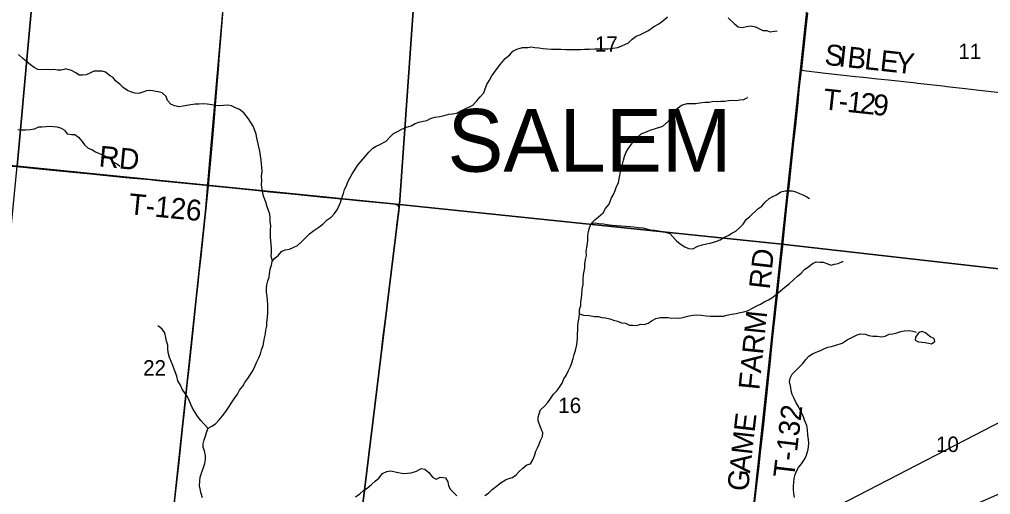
# Model space of a CAD drawing. Extents: x 831 to 1552, y 430 to 870.
# Drawn here: x 993.3 to 1046.1, y 699.2 to 725.1 of the extents above; entities that cross this region are included whole.
import ezdxf

# ---------------------------------------------------------------- set-up
doc = ezdxf.new("R2010")
doc.units = 0
for name, color, linetype in [('GM_X_Corporation', 7, 'Continuous'), ('GM_X_Minor_Lake', 7, 'Continuous'), ('GM_X_Minor_River', 7, 'Continuous'), ('GM_X_Rail_Line', 7, 'Continuous'), ('GM_X_Section_Text', 7, 'Continuous'), ('GM_X_Township_Road', 7, 'Continuous'), ('GM_X_Township_Road_Text', 7, 'Continuous'), ('GM_X_Township_Text', 7, 'Continuous'), ('GM_X_US_Route', 7, 'Continuous'), ('SH_Text', 7, 'Continuous')]:
    doc.layers.add(name, color=color, linetype=linetype)

msp = doc.modelspace()

# ---------------------------------------------------------------- linework, layer by layer
at = {"layer": 'GM_X_Corporation'}
for points in [[(974.695, 738.984), (994.975, 737.085), (993.147, 717.069), (972.322, 718.961)], [(994.975, 737.085), (1015.357, 735.031), (1013.944, 715), (993.147, 717.069)], [(1015.357, 735.031), (1036.878, 732.803), (1034.738, 712.834), (1013.944, 715)], [(1036.878, 732.803), (1052.432, 731.297), (1052.759, 730.026), (1055.607, 718.06), (1054.834, 710.548), (1034.738, 712.834)], [(993.147, 717.069), (1013.944, 715), (1011.587, 695.769), (991.236, 697.554)], [(1034.738, 712.834), (1032.694, 693.772), (1011.587, 695.769), (1013.944, 715)], [(1034.738, 712.834), (1054.834, 710.548), (1052.831, 691.774), (1032.694, 693.772)]]:
    msp.add_lwpolyline(points, close=True, dxfattribs=at)
at = {"layer": 'GM_X_Minor_Lake'}
for points in [[(1042.005, 707.771), (1041.987, 707.62), (1042.176, 707.519), (1042.358, 707.509), (1042.524, 707.492), (1042.714, 707.451), (1042.88, 707.411), (1043.005, 707.511)], [(1043.005, 707.511), (1043.057, 707.552), (1043.021, 707.711), (1042.847, 707.774), (1042.682, 707.898), (1042.555, 708.006), (1042.366, 708.091), (1042.191, 708.041), (1042.005, 707.771)]]:
    msp.add_lwpolyline(points, dxfattribs=at)
at = {"layer": 'GM_X_Minor_River'}
for points in [[(1017.272, 720.076), (1017.517, 720.195), (1017.93, 720.388), (1018.145, 720.636), (1018.33, 720.839), (1018.53, 721.072), (1018.601, 721.283), (1018.702, 721.517), (1018.833, 721.743), (1018.965, 721.991), (1019.119, 722.187), (1019.413, 722.608), (1019.697, 722.924), (1019.943, 723.134), (1020.112, 723.329), (1020.334, 723.433), (1020.632, 723.536), (1020.922, 723.534), (1021.112, 723.562), (1021.302, 723.523), (1021.53, 723.513), (1021.759, 723.473), (1022.215, 723.431), (1022.527, 723.443), (1022.725, 723.434), (1022.984, 723.424), (1023.197, 723.415), (1023.593, 723.418), (1023.791, 723.424), (1024.004, 723.437), (1024.286, 723.442), (1024.56, 723.448), (1024.797, 723.453), (1025.025, 723.458), (1025.276, 723.464), (1025.551, 723.492), (1025.81, 723.527), (1026.032, 723.616), (1026.391, 723.787), (1026.606, 723.982), (1026.821, 724.147), (1027.02, 724.213), (1027.241, 724.325), (1027.479, 724.459), (1027.755, 724.654), (1028.053, 724.81), (1028.245, 724.968), (1028.514, 725.2)], [(1031.825, 725.14), (1032.165, 724.811), (1032.369, 724.65), (1032.574, 724.618), (1032.811, 724.676), (1033.078, 724.712), (1033.298, 724.657), (1033.495, 724.556), (1033.707, 724.448), (1033.897, 724.447), (1034.11, 724.384), (1034.331, 724.412), (1034.484, 724.426)], [(995.774, 722.357), (995.547, 722.3), (995.352, 722.302), (995.155, 722.331), (994.95, 722.322), (994.753, 722.327), (994.532, 722.311), (994.282, 722.326), (994.081, 722.438), (993.872, 722.58), (993.65, 722.776), (993.458, 722.933), (993.229, 723.151)], [(1007.044, 711.927), (1006.971, 712.168), (1006.988, 712.372), (1006.983, 712.615), (1006.969, 712.82), (1006.948, 713.009), (1006.927, 713.214), (1006.929, 713.411), (1006.923, 713.608), (1006.941, 713.835), (1006.92, 714.063), (1006.907, 714.275), (1006.886, 714.472), (1006.819, 714.67), (1006.753, 714.86), (1006.693, 715.057), (1006.627, 715.262), (1006.545, 715.452), (1006.486, 715.71), (1006.436, 716.067), (1006.461, 716.271), (1006.441, 716.536), (1006.481, 716.778), (1006.461, 717.013), (1006.44, 717.202), (1006.419, 717.407), (1006.383, 717.634), (1006.355, 717.9), (1006.304, 718.12), (1006.194, 718.613), (1006.15, 718.817), (1006.084, 719.015), (1005.987, 719.25), (1005.867, 719.448), (1005.732, 719.654), (1005.483, 719.967), (1005.249, 720.15), (1005.022, 720.243), (1004.809, 720.359), (1004.604, 720.391), (1004.375, 720.37), (1004.177, 720.357), (1003.942, 720.382), (1003.736, 720.414), (1003.485, 720.447), (1003.295, 720.464), (1003.059, 720.451), (1002.83, 720.438), (1002.594, 720.402), (1002.38, 720.366), (1002.182, 720.345), (1001.938, 720.31), (1001.725, 720.35), (1001.52, 720.427), (1001.325, 720.641), (1001.258, 720.869), (1001.032, 721.06), (1000.826, 721.115), (1000.606, 721.147), (1000.416, 721.194), (1000.187, 721.174), (999.981, 721.108), (999.767, 721.019), (999.562, 721.036), (999.372, 721.091), (999.16, 721.191), (998.925, 721.36), (998.729, 721.543), (998.502, 721.712), (998.367, 721.902), (998.17, 722.002), (997.958, 722.193), (997.768, 722.241), (997.54, 722.25), (997.319, 722.245), (997.113, 722.141), (996.914, 722.037), (996.723, 722.016), (996.533, 722.025), (996.336, 722.156), (996.116, 722.279), (995.904, 722.334), (995.771, 722.359)], [(1022.182, 704.464), (1022.329, 704.675), (1022.521, 704.878), (1022.645, 705.067), (1022.784, 705.285), (1022.877, 705.512), (1023.009, 705.701), (1023.141, 705.973), (1023.242, 706.192), (1023.312, 706.381), (1023.383, 706.616), (1023.453, 706.835), (1023.524, 707.062), (1023.579, 707.297), (1023.604, 707.494), (1023.629, 707.767), (1023.631, 707.957), (1023.648, 708.161), (1023.65, 708.374), (1023.66, 708.579), (1023.708, 708.844), (1023.74, 709.071), (1023.735, 709.276), (1023.805, 709.503), (1023.799, 709.7), (1023.847, 709.897), (1023.864, 710.094), (1023.874, 710.39), (1023.93, 710.639), (1023.925, 710.897), (1023.943, 711.178), (1023.983, 711.367), (1024.015, 711.556), (1024.032, 711.746), (1024.057, 712.003), (1024.112, 712.222), (1024.092, 712.442), (1024.124, 712.647), (1024.171, 712.851), (1024.181, 713.056), (1024.191, 713.298), (1024.231, 713.518), (1024.286, 713.729), (1024.365, 713.956), (1024.572, 714.151), (1024.772, 714.316), (1025.017, 714.541), (1025.149, 714.782), (1025.342, 715.015), (1025.474, 715.347), (1025.59, 715.536), (1025.676, 715.762), (1025.747, 715.974), (1025.863, 716.177), (1025.887, 716.382), (1025.92, 716.571), (1025.96, 716.783), (1026.015, 716.979), (1026.078, 717.183), (1026.126, 717.41), (1026.188, 717.599), (1026.251, 717.795), (1026.382, 718.014), (1026.506, 718.202), (1026.668, 718.412), (1026.845, 718.615), (1027.083, 718.84), (1027.381, 718.944), (1027.58, 719.04), (1028.26, 719.246), (1028.582, 719.516), (1028.775, 719.779), (1028.86, 719.968), (1029.084, 720.231), (1029.283, 720.396), (1029.596, 720.492), (1029.794, 720.482), (1030.061, 720.48), (1030.259, 720.516), (1030.571, 720.551), (1030.792, 720.564), (1031.029, 720.607), (1031.227, 720.598), (1031.425, 720.619), (1031.63, 720.617), (1031.844, 720.653), (1032.05, 720.673), (1032.248, 720.649), (1032.446, 720.685), (1032.667, 720.706), (1032.866, 720.81), (1032.858, 720.817)], [(1003.399, 701.34), (1003.34, 701.592), (1003.265, 701.783), (1003.275, 701.972), (1003.33, 702.2), (1003.393, 702.405), (1003.456, 702.601), (1003.549, 702.836), (1003.741, 702.948), (1003.932, 703.068), (1004.14, 703.279), (1004.324, 703.497), (1004.509, 703.731), (1004.95, 704.433), (1005.127, 704.682), (1005.251, 704.901), (1005.42, 705.112), (1005.537, 705.309), (1005.706, 705.527), (1005.83, 705.731), (1005.961, 705.95), (1006.07, 706.192), (1006.179, 706.441), (1006.295, 706.661), (1006.381, 706.872), (1006.436, 707.092), (1006.53, 707.326), (1006.57, 707.523), (1006.602, 707.735), (1006.657, 707.955), (1006.675, 708.152), (1006.722, 708.379), (1006.732, 708.576), (1006.765, 708.849), (1006.79, 709.076), (1006.785, 709.357), (1006.786, 709.547), (1006.766, 709.767), (1006.745, 710.01), (1006.717, 710.207), (1006.718, 710.419), (1006.736, 710.624), (1006.776, 710.843), (1006.861, 711.04), (1006.871, 711.229), (1006.919, 711.479), (1006.989, 711.698), (1007.014, 711.887), (1007.16, 712.083), (1007.367, 712.232), (1007.529, 712.435), (1007.736, 712.524), (1007.957, 712.568), (1008.156, 712.649), (1008.4, 712.768), (1008.608, 712.956), (1008.808, 713.158), (1009.054, 713.398), (1009.284, 713.578), (1009.552, 713.757), (1009.782, 713.929), (1010.02, 714.154), (1010.235, 714.311), (1010.419, 714.507), (1010.551, 714.702), (1010.652, 714.906), (1010.745, 715.102), (1010.792, 715.298), (1010.894, 715.585), (1010.957, 715.804), (1011.066, 716.008), (1011.136, 716.227), (1011.268, 716.468), (1011.369, 716.656), (1011.508, 716.874), (1011.655, 717.108), (1011.863, 717.348), (1012.094, 717.626), (1012.286, 717.844), (1012.494, 718.061), (1012.685, 718.158), (1012.884, 718.247), (1013.213, 718.433), (1013.436, 718.666), (1013.628, 718.846), (1013.866, 718.987), (1014.072, 719.084), (1014.332, 719.195), (1014.576, 719.268), (1014.791, 719.403), (1014.997, 719.469), (1015.234, 719.52), (1015.424, 719.556), (1015.631, 719.66), (1015.86, 719.749), (1016.135, 719.776), (1016.371, 719.827), (1016.623, 719.908), (1016.829, 719.929), (1017.058, 719.965), (1017.272, 720.076)], [(995.732, 719.032), (995.523, 719.145), (995.327, 719.196), (995.123, 719.217), (994.926, 719.238), (994.735, 719.206), (994.508, 719.205), (994.317, 719.195), (994.086, 719.081), (993.865, 719.05), (993.607, 719.027), (993.41, 719.041), (993.19, 719.047)], [(995.732, 719.032), (995.878, 718.838), (996.099, 718.805), (996.289, 718.803), (996.493, 718.658), (996.666, 718.429), (996.809, 718.239), (997.021, 718.062), (997.21, 717.977), (997.415, 717.862), (997.612, 717.762), (997.801, 717.684), (997.999, 717.607), (998.195, 717.491), (998.392, 717.293), (998.604, 717.177), (998.74, 717.085)], [(1024.376, 713.966), (1024.586, 713.992), (1024.783, 713.967), (1025.042, 713.934), (1025.232, 713.902), (1025.506, 713.869), (1025.749, 713.852), (1026.008, 713.834), (1026.236, 713.809), (1026.488, 713.791), (1026.693, 713.782), (1026.921, 713.749), (1027.18, 713.731), (1027.385, 713.669), (1027.583, 713.621), (1027.811, 713.589), (1028.024, 713.557), (1028.267, 713.531), (1028.464, 713.469), (1028.654, 713.414), (1028.828, 713.215), (1029.008, 713.024), (1029.212, 712.847), (1029.462, 712.693), (1029.667, 712.6), (1029.903, 712.575), (1030.163, 712.724), (1030.4, 712.79), (1030.644, 712.849), (1030.842, 712.892), (1031.14, 712.98), (1031.385, 713.069), (1031.576, 713.203), (1031.821, 713.3), (1032.02, 713.434), (1032.227, 713.546), (1032.45, 713.749), (1032.641, 713.921), (1032.796, 714.17), (1033.003, 714.342), (1033.434, 714.763), (1033.648, 714.905), (1033.833, 715.115), (1034.04, 715.31), (1034.239, 715.422), (1034.453, 715.519), (1034.691, 715.676), (1034.92, 715.726), (1035.11, 715.732), (1035.308, 715.738), (1035.498, 715.683), (1035.695, 715.59), (1035.885, 715.512), (1036.09, 715.404), (1036.241, 715.327)], [(1023.736, 709.039), (1023.945, 708.97), (1024.257, 708.952), (1024.554, 708.904), (1024.752, 708.909), (1024.949, 708.854), (1025.154, 708.822), (1025.375, 708.774), (1025.587, 708.704), (1025.808, 708.641), (1026.02, 708.563), (1026.241, 708.538), (1026.453, 708.437), (1026.643, 708.435), (1026.849, 708.418), (1027.055, 708.492), (1027.245, 708.475), (1027.467, 708.541), (1027.681, 708.683), (1027.888, 708.795), (1028.117, 708.846), (1028.338, 708.851), (1028.558, 708.849), (1028.749, 708.817), (1028.962, 708.83), (1029.198, 708.812), (1029.434, 708.87), (1029.702, 708.936), (1029.892, 708.98), (1030.098, 708.993), (1030.349, 708.975), (1030.631, 708.942), (1030.866, 708.925), (1031.316, 708.92), (1031.559, 708.925), (1031.75, 708.969), (1031.995, 709.035), (1032.246, 709.07), (1032.467, 709.121), (1032.673, 709.157), (1032.872, 709.216), (1033.147, 709.35), (1033.385, 709.484), (1033.576, 709.581), (1033.813, 709.715), (1034.004, 709.812), (1034.196, 709.916), (1034.433, 710.096), (1034.656, 710.291), (1034.902, 710.493), (1035.147, 710.703), (1035.393, 710.921), (1035.593, 711.101), (1035.785, 711.266), (1035.992, 711.484), (1036.184, 711.596), (1036.398, 711.776), (1036.597, 711.872), (1036.803, 711.863), (1036.993, 711.853), (1037.183, 711.776), (1037.41, 711.697), (1037.601, 711.756), (1037.807, 711.777), (1038.037, 711.896), (1038.075, 711.896)], [(1003.538, 702.808), (1003.323, 703.043), (1003.142, 703.25), (1002.961, 703.488), (1002.788, 703.732), (1002.676, 703.961), (1002.519, 704.297), (1002.415, 704.533), (1002.295, 704.724), (1002.129, 704.946), (1002.04, 705.175), (1001.89, 705.412), (1001.831, 705.663), (1001.69, 706.036), (1001.616, 706.234), (1001.519, 706.455), (1001.445, 706.669), (1001.356, 706.943), (1001.342, 707.14), (1001.344, 707.337), (1001.278, 707.558), (1001.242, 707.763), (1001.175, 708.007), (1001.033, 708.205), (1000.836, 708.374), (1000.798, 708.382)], [(1036.023, 706.55), (1036.2, 706.753), (1036.399, 706.881), (1036.605, 706.962), (1036.796, 707.028), (1036.987, 707.118), (1037.232, 707.237), (1037.446, 707.272), (1037.675, 707.338), (1038.018, 707.449), (1038.287, 707.636), (1038.501, 707.748), (1038.83, 707.911), (1039.021, 707.963), (1039.272, 707.945), (1039.469, 707.867), (1039.682, 707.827), (1039.918, 707.825), (1040.154, 707.792), (1040.352, 707.828), (1040.581, 707.94), (1040.78, 707.953), (1040.986, 708.011), (1041.2, 708.085), (1041.39, 708.129), (1041.665, 708.149), (1041.855, 708.109), (1042.045, 708.054), (1042.037, 708.054)], [(1035.429, 699.057), (1035.385, 699.286), (1035.364, 699.491), (1035.373, 699.689), (1035.398, 699.886), (1035.408, 700.099), (1035.455, 700.304), (1035.541, 700.493), (1035.649, 700.689), (1035.811, 700.893), (1035.958, 701.112), (1036.058, 701.301), (1036.121, 701.49), (1036.168, 701.68), (1036.202, 701.991), (1036.189, 702.227), (1036.145, 702.44), (1036.133, 702.767), (1036.089, 702.98), (1035.97, 703.27), (1035.903, 703.498), (1035.783, 703.705), (1035.641, 704.018), (1035.521, 704.209), (1035.402, 704.438), (1035.305, 704.659), (1035.246, 704.857), (1035.232, 705.047), (1035.159, 705.359), (1035.183, 705.556), (1035.3, 705.768), (1035.615, 706.068), (1035.876, 706.339), (1036.023, 706.55)], [(1018.578, 699.179), (1018.785, 699.291), (1018.985, 699.495), (1019.215, 699.683), (1019.468, 699.878), (1019.705, 700.02), (1019.896, 700.094), (1020.095, 700.153), (1020.286, 700.288), (1020.448, 700.484), (1020.655, 700.657), (1020.878, 700.829), (1021.076, 700.896), (1021.2, 701.115), (1021.278, 701.32), (1021.364, 701.577), (1021.457, 701.766), (1021.535, 701.963), (1021.613, 702.152), (1021.722, 702.371), (1021.731, 702.577), (1021.649, 702.798), (1021.553, 703.034), (1021.493, 703.225), (1021.48, 703.422), (1021.535, 703.619), (1021.621, 703.831), (1021.828, 704.027), (1022.005, 704.23), (1022.182, 704.464)], [(1003.225, 699.046), (1003.159, 699.274), (1003.071, 699.701), (1003.081, 699.952), (1003.106, 700.165), (1003.2, 700.445), (1003.286, 700.688), (1003.356, 700.907), (1003.389, 701.12), (1003.399, 701.34)], [(1011.556, 699.096), (1011.786, 699.261), (1011.986, 699.441), (1012.178, 699.569), (1012.431, 699.771), (1012.63, 699.952), (1012.83, 700.117), (1013.015, 700.359), (1013.259, 700.478), (1013.481, 700.514), (1013.777, 700.443), (1014.157, 700.371), (1014.386, 700.384), (1014.584, 700.404), (1014.874, 700.5), (1015.127, 700.642), (1015.317, 700.61), (1015.543, 700.418), (1015.732, 700.173), (1015.936, 700.064), (1016.15, 700.169), (1016.455, 700.135), (1016.574, 699.906), (1016.611, 699.7), (1016.723, 699.494), (1017.07, 699.149)]]:
    msp.add_lwpolyline(points, dxfattribs=at)
at = {"layer": 'GM_X_Rail_Line'}
msp.add_lwpolyline([(997.388, 650.938), (997.987, 656.381), (998.443, 662.173), (999.567, 676.345), (1001.482, 696.666), (1003.414, 714.776), (1003.551, 716.542), (1004.517, 727.567), (1005.667, 742.027), (1005.605, 743.565), (1005.257, 745.206), (1004.732, 746.62), (1003.92, 748.118), (1002.725, 749.701), (998.874, 754.713), (995.664, 758.989), (994.502, 760.652), (993.842, 762.104), (993.466, 763.719), (993.405, 765.341), (993.538, 767.661), (994.84, 786.938)], dxfattribs=at)
at = {"layer": 'GM_X_Township_Road'}
for points in [[(1036.136, 725.397), (1036.047, 724.593), (1035.95, 723.729), (1035.823, 722.543), (1035.799, 722.288)], [(1033.273, 698.804), (1033.328, 699.306), (1033.431, 700.207), (1033.48, 700.627), (1033.579, 701.516), (1033.699, 702.577), (1033.773, 703.219), (1033.833, 703.763), (1033.923, 704.615), (1034.032, 705.653), (1034.099, 706.313), (1034.198, 707.264), (1034.311, 708.31), (1034.356, 708.755), (1034.427, 709.434), (1034.481, 709.903), (1034.685, 711.768), (1034.787, 712.719), (1034.873, 713.497), (1034.981, 714.548), (1035.071, 715.413), (1035.131, 715.944), (1035.265, 717.179), (1035.374, 718.242), (1035.493, 719.304), (1035.624, 720.54), (1035.706, 721.406), (1035.782, 722.11), (1035.799, 722.288)], [(1035.799, 722.288), (1035.93, 722.273), (1037.103, 722.134), (1038.746, 721.949), (1039.161, 721.906)], [(1039.161, 721.906), (1039.932, 721.825), (1040.538, 721.763), (1042.043, 721.598), (1042.122, 721.589)], [(1042.122, 721.589), (1043.325, 721.454), (1043.498, 721.435), (1043.708, 721.412), (1044.7, 721.295), (1045.64, 721.192), (1046.604, 721.075), (1047.548, 720.97), (1048.152, 720.903), (1048.424, 720.874), (1048.72, 720.839), (1049.288, 720.772), (1049.893, 720.703), (1050.461, 720.639), (1051.289, 720.544), (1051.709, 720.497), (1053.43, 720.304)], [(1003.556, 716.012), (1003.393, 716.028), (1001.724, 716.194), (1000.784, 716.284), (1000.363, 716.326), (999.249, 716.43), (998.173, 716.531), (997.134, 716.635), (995.811, 716.766), (995.255, 716.822), (994.352, 716.909), (993.474, 716.997), (992.46, 717.096)], [(1012.022, 699.2), (1012.08, 699.706), (1012.182, 700.607), (1012.319, 701.704), (1012.422, 702.505), (1012.552, 703.554), (1012.663, 704.466), (1012.747, 705.17), (1012.845, 705.959), (1012.898, 706.378), (1012.949, 706.822), (1013.028, 707.535), (1013.079, 707.97), (1013.168, 708.628), (1013.225, 709.08), (1013.358, 710.103), (1013.427, 710.665), (1013.514, 711.418), (1013.582, 711.972), (1013.643, 712.441), (1013.71, 712.988), (1013.776, 713.611), (1013.809, 713.873), (1013.844, 714.128), (1013.901, 714.488), (1013.925, 714.67), (1013.929, 714.709), (1013.931, 714.739), (1013.932, 714.765), (1013.929, 714.789), (1013.927, 714.812), (1013.921, 714.832), (1013.916, 714.848), (1013.909, 714.862), (1013.896, 714.882), (1013.882, 714.901), (1013.868, 714.919), (1013.854, 714.933), (1013.835, 714.948), (1013.817, 714.96), (1013.794, 714.973), (1013.768, 714.984), (1013.744, 714.993), (1013.711, 715.002), (1013.681, 715.009), (1013.646, 715.014), (1013.611, 715.019), (1013.545, 715.026), (1013.442, 715.034), (1012.826, 715.084), (1012.442, 715.119), (1011.675, 715.19), (1011.192, 715.238), (1009.809, 715.378), (1008.262, 715.529), (1006.889, 715.668), (1006.098, 715.747), (1004.85, 715.877), (1003.556, 716.012)]]:
    msp.add_lwpolyline(points, dxfattribs=at)
at = {"layer": 'GM_X_US_Route'}
msp.add_lwpolyline([(1001.663, 698.241), (1001.804, 699.566), (1001.94, 700.827), (1002.162, 702.915), (1002.267, 703.879), (1002.423, 705.324), (1002.502, 706.077), (1002.706, 707.968), (1002.931, 710.056), (1002.999, 710.686), (1003.059, 711.267), (1003.156, 712.156), (1003.322, 713.738), (1003.556, 716.012), (1003.688, 717.394), (1003.797, 718.623), (1003.826, 719.032), (1004.01, 721.299), (1004.096, 722.339), (1004.158, 723.144), (1004.206, 723.789), (1004.39, 726.022)], dxfattribs=at)
at = {"layer": 'SH_Text'}
msp.add_lwpolyline([(995.67, 676.817), (1119.5, 731.442), (1119.5, 740.878)], close=True, dxfattribs=at)

# ---------------------------------------------------------------- texts
at = {"layer": 'GM_X_Section_Text'}
for s, p in [('17', (1024.571, 723.296)), ('11', (1044.338, 722.902)), ('22', (1000.004, 705.691)), ('16', (1022.579, 703.652)), ('10', (1043.121, 701.535))]:
    msp.add_text(s, height=0.8371, rotation=0, dxfattribs=at).set_placement(p)
at = {"layer": 'GM_X_Township_Road_Text'}
for s, height, rotation, p in [('S', 1.136, 352.9598, (1037.018, 722.605)), ('I', 1.136, 353.7659, (1037.796, 722.509)), ('B', 1.136, 353.7923, (1038.26, 722.458)), ('L', 1.136, 353.7909, (1039.188, 722.357)), ('E', 1.136, 353.7928, (1040.033, 722.265)), ('Y', 1.136, 353.7914, (1040.878, 722.173)), ('T', 1.136, 353.8122, (1036.942, 720.173)), ('1', 1.136, 353.8344, (1038.251, 720.031)), ('2', 1.136, 353.9182, (1038.949, 719.956)), ('9', 1.136, 354.1636, (1039.65, 719.881)), ('-', 1.136, 353.8195, (1037.787, 720.081)), ('RD', 1.1364, 354.5823, (997.563, 717.062)), ('T-126', 1.1364, 354.4276, (999.177, 714.471)), ('RD', 1.1364, 83.6054, (1034.077, 710.35)), ('FARM', 1.1364, 84.1976, (1033.509, 704.878)), ('T-132', 1.1364, 83.2931, (1035.397, 700.091)), ('E', 1.136, 83.2476, (1033.25, 702.578)), ('M', 1.136, 83.6546, (1033.114, 701.354)), ('A', 1.136, 83.6594, (1033.004, 700.361)), ('G', 1.136, 83.6594, (1032.893, 699.367))]:
    msp.add_text(s, height=height, rotation=rotation, dxfattribs=at).set_placement(p)
at = {"layer": 'GM_X_Township_Text'}
msp.add_text('SALEM', height=3.4091, rotation=0, dxfattribs=at).set_placement((1016.555, 716.775))

doc.saveas('drawing.dxf')
